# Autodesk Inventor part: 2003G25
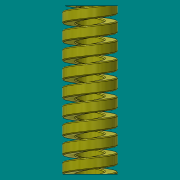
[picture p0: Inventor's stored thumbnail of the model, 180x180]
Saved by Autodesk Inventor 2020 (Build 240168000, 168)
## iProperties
Created: 2016-03
Part Number: 2003G25
Material: Steel
Document SubType Name: Modeling
Designer: Jonas
Density: 6e-05 g/cm^3
Appearance: Yellow
Mass: 0.00104552 g
Surface Area: 123.395 cm^2
Volume: 17.4254 cm^3
Author: Jonas
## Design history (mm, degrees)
sketch "Sketch2"
  geometry: C1 r 6.5 at (0, 0); C2 r 12.5 at (0, 0); 1 further point
  constraints: 2 centre point, 2 coincident
  dimensions: "d4" = 13 diameter of C1; "d20" = 25 diameter of C2
extrude "Extrusion1" new body sketch "Sketch2" taper "d6" = 0 deg; distance "Höjd" = 115
sketch "Sketch1"
  geometry: L1 (0, 0)-(0, 44.652); L2 (0, 0)-(0, 4.612); L3 (6.5, 0)-(12.5, 0); L4 (12.5, 0)-(12.5, -3); L5 (12.5, -3)-(6.5, -3); L6 (6.5, -3)-(6.5, 0); 1 further point
  constraints: 12 end point, 3 vertical, 2 horizontal, 1 horizontal alignment, 1 midpoint, 1 point on line, 1 vertical alignment
  dimensions: "d8" = 25 diameter of L3.end L1; "d10" = 3 distance of L3.end L4.end; "d22" = 13 diameter of L6 L1
coil "Coil1" sketch "Sketch1" pitch "d12" = 8.5; turns "d14" = 1; dims "d13" = 120 (computed from Höjd), "d15" = 0, angle "d16" = 90 deg, angle "d17" = 90 deg, "d18" = 0, "d19" = 0
fillet "Fillet1" dims "d23" = 0.5
body "Solid1"
